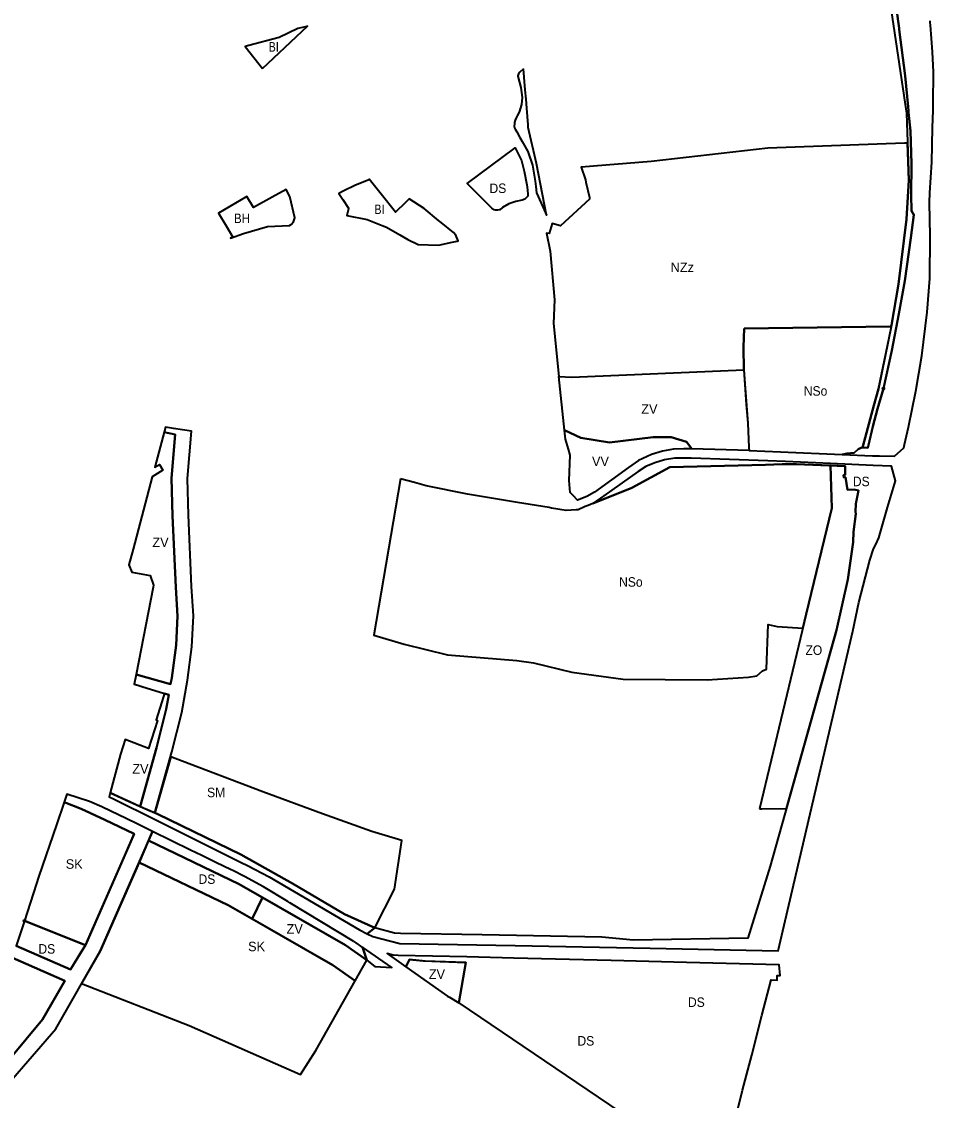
# Model space of a CAD drawing. Extents: x -650276 to -642489, y -1074311 to -1066658.
# Drawn here: x -646121 to -644970, y -1071573 to -1070212 of the extents above; entities that cross this region are included whole.
import ezdxf

# ---------------------------------------------------------------- set-up
doc = ezdxf.new("R2010")
doc.units = 0
doc.header["$LTSCALE"] = 4.8
doc.header["$PDMODE"] = 32
doc.header["$PDSIZE"] = 2.4
for name, color, linetype, lineweight in [('1', 7, 'Continuous', 35), ('11', 7, 'Continuous', 35), ('15', 7, 'Continuous', 35), ('18', 7, 'Continuous', 35), ('2', 7, 'Continuous', 35), ('20', 7, 'Continuous', 35), ('24', 7, 'Continuous', 35), ('40', 7, 'Continuous', 35), ('42', 7, 'Continuous', 35), ('45', 7, 'Continuous', 35), ('46', 7, 'Continuous', 35), ('56', 7, 'Continuous', 35)]:
    doc.layers.add(name, color=color, linetype=linetype, lineweight=lineweight)
doc.layers.add('62', color=7, linetype='Continuous')
doc.layers.add('63', color=7, linetype='Continuous')

msp = doc.modelspace()

# ---------------------------------------------------------------- linework, layer by layer
at = {"layer": '1'}
msp.add_lwpolyline([(-645862.66, -1070469.5), (-645853.98, -1070483.81), (-645856.87, -1070485.24), (-645840.59, -1070479), (-645810.44, -1070470.17), (-645782.57, -1070469.22), (-645780.38, -1070467.64), (-645777.8, -1070464.4), (-645776.04, -1070459.38), (-645782.13, -1070432.59), (-645786.9, -1070423.81), (-645804.58, -1070433.53), (-645828.24, -1070446.54), (-645836.32, -1070432.55), (-645872.35, -1070453.55)], close=True, dxfattribs=at)
at = {"layer": '11'}
msp.add_lwpolyline([(-646066.165, -1071422.155), (-646153.5, -1071383.85), (-646208.577, -1071360.044), (-646241.68, -1071416.887), (-646258.487, -1071439.265), (-646275.615, -1071460.886), (-646289.976, -1071477.514), (-646330.914, -1071521.11), (-646324, -1071535), (-646217.978, -1071613.552), (-646211.407, -1071606.247), (-646156.471, -1071545.166), (-646094.063, -1071471.007)], close=True, dxfattribs=at)
at = {"layer": '15'}
for points in [[(-645065.235, -1070011.695), (-645056.555, -1070026.163), (-645050.293, -1070047.035), (-645043.92, -1070076.344), (-645034.122, -1070126.616), (-645004.791, -1070324.889), (-645004.523, -1070326.697)], [(-645033.53, -1070674.55), (-645022.64, -1070626.93), (-645014.07, -1070580.72), (-645006.44, -1070538.78), (-644998.92, -1070484.58), (-644995.14, -1070455.72), (-644998.17, -1070450.59), (-644998.25, -1070430.5), (-644997.87, -1070391.16), (-644999.47, -1070349.63), (-645001.64, -1070326.4), (-645001.81, -1070324.58), (-645002.308, -1070319.268), (-645005.98, -1070280.14), (-645013.51, -1070222.04), (-645013.77, -1070220.04), (-645016.92, -1070196.32)], [(-645487.361, -1070271.37), (-645491.94, -1070275.85), (-645491.94, -1070275.85), (-645493.8, -1070277.67), (-645494.57, -1070280.34), (-645494.12, -1070282.52), (-645490.79, -1070294.93), (-645489.31, -1070307.77), (-645490.03, -1070316.27), (-645493.05, -1070326.11), (-645495.44, -1070330.67), (-645496.12, -1070332.34), (-645497.83, -1070336.16), (-645498.75, -1070338.98), (-645499.01, -1070340.96), (-645499.09, -1070343.91), (-645498.74, -1070345.87), (-645498, -1070347.74), (-645496.02, -1070351.15), (-645491.97, -1070358.14), (-645488.99, -1070362.96)], [(-645487.361, -1070271.37), (-645491.94, -1070275.85), (-645491.94, -1070275.85), (-645493.8, -1070277.67), (-645494.57, -1070280.34), (-645494.12, -1070282.52), (-645490.79, -1070294.93), (-645489.31, -1070307.77), (-645490.03, -1070316.27), (-645493.05, -1070326.11), (-645495.44, -1070330.67), (-645496.12, -1070332.34), (-645497.83, -1070336.16), (-645498.75, -1070338.98), (-645499.01, -1070340.96), (-645499.09, -1070343.91), (-645498.74, -1070345.87), (-645498, -1070347.74), (-645496.02, -1070351.15), (-645491.97, -1070358.14)], [(-645458.32, -1070455.91), (-645471, -1070391), (-645481.67, -1070345.39), (-645481.65, -1070342.07), (-645483.34, -1070321.17), (-645484.27, -1070309.7), (-645485.21, -1070298.03), (-645487.361, -1070271.37)], [(-645483.34, -1070321.17), (-645484.27, -1070309.7), (-645485.21, -1070298.03), (-645487.361, -1070271.37)], [(-645482.16, -1070375.96), (-645476.12, -1070393.13), (-645472.61, -1070413.13), (-645471.87, -1070419.96), (-645470.99, -1070428.07), (-645461.32, -1070449.31), (-645458.32, -1070455.91), (-645471, -1070391), (-645481.67, -1070345.39), (-645481.65, -1070342.07), (-645483.34, -1070321.17)], [(-645004.523, -1070326.697), (-645004.434, -1070327.302), (-645001.312, -1070412.099), (-645004.327, -1070461.264), (-645014.277, -1070543.11), (-645023.048, -1070595.033), (-645039.574, -1070675.065)], [(-645491.97, -1070358.14), (-645488.99, -1070362.96), (-645482.16, -1070375.96)], [(-645488.99, -1070362.96), (-645482.16, -1070375.96), (-645476.12, -1070393.13), (-645472.61, -1070413.13), (-645471.87, -1070419.96), (-645470.99, -1070428.07), (-645461.32, -1070449.31), (-645458.32, -1070455.91)], [(-645039.574, -1070675.065), (-645045.493, -1070696.321), (-645059.308, -1070747.712), (-645059.403, -1070749.195), (-645053.21, -1070749.75), (-645052.4, -1070746.427), (-645046.63, -1070722.77), (-645041, -1070700.44), (-645033.53, -1070674.55)], [(-646197.398, -1071620.579), (-646077.593, -1071482.499), (-646021.674, -1071384.575), (-645964.396, -1071254.314), (-645955.342, -1071233.725), (-645973.324, -1071224.925), (-645989.7, -1071216.91), (-645997.62, -1071213.03), (-646019.41, -1071202.36), (-646035.06, -1071195.87), (-646063.59, -1071186.33), (-646067.097, -1071196.699), (-646045.462, -1071204.917), (-646015.387, -1071218.854), (-645978.403, -1071236.481), (-646040.084, -1071376.813), (-646058.719, -1071407.796), (-646127.301, -1071378.036)], [(-645701.44, -1071372.25), (-645782.32, -1071323.5), (-645784.92, -1071321.93), (-645815.65, -1071303.41), (-645839.37, -1071290.6), (-645854.1, -1071282.93), (-645856.26, -1071281.91), (-645875.48, -1071272.81), (-645893.41, -1071264.04), (-645907.62, -1071257.08), (-645955.342, -1071233.725), (-645960.34, -1071245.09), (-645846, -1071300), (-645712, -1071377), (-645712, -1071377)], [(-645712, -1071377), (-645685.098, -1071395.824), (-645690.677, -1071379.721)], [(-646132.229, -1071393.179), (-646066.165, -1071422.155), (-646094.063, -1071471.007), (-646156.471, -1071545.166)]]:
    msp.add_lwpolyline(points, dxfattribs=at)
for points in [[(-645911.345, -1070788.463), (-645906.373, -1070728.716), (-645929.077, -1070725.068), (-645939.27, -1070723.43), (-645940.955, -1070729.799), (-645926.784, -1070732.812), (-645931.369, -1070787.913), (-645930.036, -1070835.367), (-645926.084, -1070925.481), (-645923.919, -1070961.855), (-645925.626, -1070998.754), (-645931.24, -1071039.686), (-645932.635, -1071047.688), (-645976.17, -1071035.39), (-645978.58, -1071047.68), (-645973.77, -1071049.17), (-645968.97, -1071050.66), (-645940.25, -1071059.59), (-645934.978, -1071061.119), (-645938.15, -1071079.311), (-645950.283, -1071128.057), (-645970.966, -1071202.169), (-645952.419, -1071210.117), (-645930.943, -1071133.161), (-645918.57, -1071083.449), (-645911.474, -1071042.764), (-645905.69, -1071000.578), (-645903.891, -1070961.723), (-645906.11, -1070924.449), (-645910.048, -1070834.649)], [(-645694.15, -1071357.83), (-645684.785, -1071362.539), (-645674.947, -1071355.071), (-645713.428, -1071337.765), (-645778.69, -1071299.362), (-645844.079, -1071262.487), (-645948.761, -1071211.885), (-645967, -1071204), (-646008.714, -1071184.746), (-646010.14, -1071190.08), (-646004.65, -1071192.55), (-645951.118, -1071219.11), (-645843.45, -1071272.53), (-645835.76, -1071276.35), (-645808.13, -1071290.78), (-645795.97, -1071297.93), (-645694.15, -1071357.83)]]:
    msp.add_lwpolyline(points, close=True, dxfattribs=at)
msp.add_arc((-645538.107, -1071148.434), 277.076, 233.87926, 236.5888, dxfattribs=at)
msp.add_point((-645033.53, -1070674.55), dxfattribs=at)
at = {"layer": '18'}
for points in [[(-645926.81, -1071141.595), (-645932.502, -1071139.426), (-645952.419, -1071210.117), (-645948.761, -1071211.885)], [(-645678.86, -1071233.58), (-645741.09, -1071211.36), (-645816.47, -1071183.63), (-645926.81, -1071141.595)], [(-645948.761, -1071211.885), (-645844.079, -1071262.487), (-645778.69, -1071299.362), (-645713.428, -1071337.765), (-645674.947, -1071355.071)], [(-645674.947, -1071355.071), (-645650.09, -1071306.433), (-645640.737, -1071244.963), (-645678.86, -1071233.58)]]:
    msp.add_lwpolyline(points, dxfattribs=at)
at = {"layer": '2'}
for points in [[(-645816.9, -1070270.96), (-645760.05, -1070217.79), (-645760.91, -1070217.98), (-645772.08, -1070220.39), (-645795.85, -1070231.81), (-645833.92, -1070241.96), (-645838.53, -1070243.19)], [(-645594.769, -1070494.065), (-645577.47, -1070490.3), (-645571.13, -1070488.89), (-645569.97, -1070488.3), (-645572.86, -1070481.41), (-645575.7, -1070477.77), (-645591.49, -1070465.19), (-645594.62, -1070462.7), (-645612.77, -1070447.82), (-645631.63, -1070435.3), (-645636.42, -1070439.93), (-645648.9, -1070452.38), (-645666.99, -1070429.58), (-645682.02, -1070410.65), (-645683.52, -1070411.71), (-645699.33, -1070418.25), (-645714.74, -1070425.84), (-645720.48, -1070428.75), (-645715.56, -1070436.27), (-645708.28, -1070447.28), (-645708.42, -1070447.94), (-645710.14, -1070456.31), (-645684.78, -1070461.52), (-645665.6, -1070469.04), (-645660.29, -1070471.12), (-645643.4, -1070481.02), (-645633.35, -1070486.91), (-645620.22, -1070493)]]:
    msp.add_lwpolyline(points, close=True, dxfattribs=at)
at = {"layer": '20'}
for points in [[(-645990.48, -1071263.958), (-645978.403, -1071236.481), (-646015.387, -1071218.854), (-646045.462, -1071204.917), (-646067.097, -1071196.699), (-646076.713, -1071225.138)], [(-646076.713, -1071225.138), (-646098.66, -1071290.03), (-646102.011, -1071300.326), (-646117.031, -1071346.48)], [(-646117.031, -1071346.48), (-646040.084, -1071376.813), (-645990.48, -1071263.958)]]:
    msp.add_lwpolyline(points, dxfattribs=at)
msp.add_lwpolyline([(-645699.825, -1071422.134), (-645728.105, -1071402.346), (-645859.986, -1071326.563), (-645972.422, -1071272.568), (-646021.674, -1071384.575), (-646044.948, -1071425.333), (-645909.13, -1071478.56), (-645768.62, -1071540.17), (-645749.631, -1071509.908)], close=True, dxfattribs=at)
msp.add_point((-646117.031, -1071346.48), dxfattribs=at)
at = {"layer": '24'}
for points in [[(-645016.92, -1070196.32), (-645013.77, -1070220.04), (-645013.51, -1070222.04), (-645005.98, -1070280.14), (-645002.308, -1070319.268), (-645001.81, -1070324.58), (-645001.64, -1070326.4), (-644999.47, -1070349.63), (-644997.87, -1070391.16), (-644998.25, -1070430.5), (-644998.17, -1070450.59), (-644995.14, -1070455.72), (-644998.92, -1070484.58), (-645006.44, -1070538.78), (-645014.07, -1070580.72), (-645022.64, -1070626.93), (-645033.53, -1070674.55)], [(-645033.53, -1070674.55), (-645041, -1070700.44), (-645046.63, -1070722.77), (-645052.4, -1070746.427), (-645053.21, -1070749.75), (-645060.46, -1070749.1), (-645065.17, -1070751.39), (-645070.3, -1070755.92), (-645079.38, -1070756.91), (-645085.58, -1070758.04), (-645047.39, -1070759.71), (-645038.44, -1070759.83), (-645019.57, -1070760.07), (-645007.68, -1070749.5), (-645006.739, -1070745.384), (-645001.71, -1070723.39), (-644997.14, -1070700.88), (-644992.6, -1070677.92), (-644985.04, -1070633.43), (-644978.44, -1070578.56), (-644975.05, -1070536.16), (-644974.44, -1070482.48), (-644975.29, -1070440.14), (-644974.69, -1070427.86), (-644972.48, -1070389.15), (-644971.37, -1070345.98), (-644970.61, -1070323.44), (-644970.55, -1070321.56), (-644970.524, -1070315.358), (-644970.36, -1070275.49), (-644971.47, -1070250.14), (-644974, -1070216.2), (-644974.29, -1070213.17), (-644974.49, -1070210.98)], [(-645222.48, -1071606.08), (-645211.27, -1071560.01), (-645199.61, -1071515.68), (-645186.67, -1071465.55), (-645175.06, -1071420.93), (-645167.58, -1071421.19), (-645167.37, -1071415.2), (-645163.56, -1071415.3), (-645164.76, -1071401.79), (-645281.92, -1071398.82), (-645376.87, -1071396.41), (-645499.65, -1071393.3), (-645558.9, -1071391.8), (-645645.368, -1071389.96), (-645651.93, -1071389.82), (-645659.6, -1071387.71), (-645647.727, -1071396.036), (-645635.795, -1071404.403), (-645631.44, -1071394.9), (-645614.201, -1071396.844), (-645560.11, -1071398.7), (-645569.07, -1071449.88), (-645501.37, -1071495.68), (-645393.34, -1071568.75), (-645324.17, -1071615.53)]]:
    msp.add_lwpolyline(points, dxfattribs=at)
for points in [[(-645497.81, -1070370.93), (-645497.81, -1070370.93), (-645490.19, -1070386.97), (-645486.54, -1070400.38), (-645483.29, -1070417.99), (-645482.62, -1070423.93), (-645481.93, -1070430.04), (-645482.18, -1070432.13), (-645485.67, -1070435.7), (-645489.34, -1070437.05), (-645497.33, -1070438.82), (-645505.88, -1070441.74), (-645513.81, -1070446.24), (-645517.44, -1070449.23), (-645517.95, -1070449.45), (-645520.4, -1070449.87), (-645521.41, -1070449.84), (-645522.95, -1070449.61), (-645524.42, -1070449.16), (-645525.75, -1070448.41), (-645527.34, -1070447.1), (-645558.36, -1070416.1)], [(-645081.85, -1070781.59), (-645081.57, -1070783.53), (-645083.95, -1070783.89), (-645083.49, -1070786.92), (-645081.13, -1070786.56), (-645081.13, -1070786.56), (-645078.85, -1070802.46), (-645070.2, -1070802.33), (-645065.01, -1070803.22), (-645068.07, -1070820.37), (-645068.52, -1070830.52), (-645068.07, -1070832.72), (-645071.18, -1070855.63), (-645071.77, -1070868.73), (-645078.23, -1070915.65), (-645092.67, -1070979.52), (-645176.14, -1071277.26), (-645204.341, -1071368.19), (-645348.55, -1071370.559), (-645388.619, -1071366.991), (-645539.738, -1071364.092), (-645642.431, -1071362.259), (-645650.28, -1071362.07), (-645674.947, -1071355.071), (-645684.785, -1071362.539), (-645677.58, -1071366.16), (-645643.56, -1071374.75), (-645497.84, -1071377.53), (-645327.76, -1071380.76), (-645166.34, -1071384.07), (-645071.99, -1070980.72), (-645064.39, -1070944.7), (-645050.47, -1070891.48), (-645045.74, -1070877.19), (-645043, -1070871.35), (-645039.25, -1070863.33), (-645028.25, -1070824.83), (-645018.18, -1070791.34), (-645023.25, -1070772.62), (-645046.46, -1070771.98), (-645100.32, -1070769.5), (-645156.988, -1070766.884), (-645179.18, -1070765.86), (-645275.8, -1070762.66), (-645296.51, -1070762.52), (-645309.78, -1070764.88), (-645321.9, -1070768.47), (-645333.12, -1070773.33), (-645342.94, -1070779.31), (-645385.99, -1070810.35), (-645400.05, -1070819.84), (-645351, -1070800), (-645303, -1070774), (-645182, -1070771), (-645161, -1070770), (-645143, -1070770), (-645081.75, -1070772.79)], [(-645829.706, -1071343.963), (-645816.714, -1071316.828), (-645846, -1071300), (-645960.34, -1071245.09), (-645972.422, -1071272.568), (-645859.986, -1071326.563)], [(-646045.393, -1071385.64), (-646040.084, -1071376.813), (-646117.031, -1071346.48), (-646127.301, -1071378.036), (-646058.719, -1071407.796)], [(-645675.177, -1071403.922), (-645675.177, -1071403.922), (-645653.742, -1071405.36), (-645690.677, -1071379.721), (-645685.098, -1071395.824)]]:
    msp.add_lwpolyline(points, close=True, dxfattribs=at)
msp.add_point((-645033.53, -1070674.55), dxfattribs=at)
at = {"layer": '40'}
for points in [[(-645442.836, -1070659.455), (-645426.34, -1070660.33), (-645209.41, -1070651.2), (-645206.7, -1070694.76), (-645204.66, -1070718.51), (-645203.13, -1070749.36), (-645202.96, -1070752.89), (-645275.236, -1070750.954), (-645282, -1070742), (-645301, -1070736), (-645324, -1070736), (-645379, -1070743), (-645415, -1070737), (-645435.711, -1070727.497)], [(-645932.635, -1071047.688), (-645931.24, -1071039.686), (-645925.626, -1070998.754), (-645923.919, -1070961.855), (-645926.084, -1070925.481), (-645930.036, -1070835.367), (-645931.369, -1070787.913), (-645926.784, -1070732.812), (-645940.955, -1070729.799), (-645952.65, -1070773.98), (-645946.81, -1070770.47), (-645942.3, -1070777.96), (-645955.86, -1070786.21), (-645980.01, -1070877.28), (-645985.28, -1070897.13), (-645981.48, -1070906.35), (-645958.21, -1070910.84), (-645954.01, -1070922.8), (-645954.492, -1070925.251), (-645976.17, -1071035.39)], [(-645970.966, -1071202.169), (-645950.283, -1071128.057), (-645938.15, -1071079.311), (-645934.978, -1071061.119), (-645940.25, -1071059.59), (-645941.45, -1071063.3), (-645950.96, -1071092.8), (-645949.21, -1071093.62), (-645960.66, -1071128.71), (-645990.14, -1071117.76), (-645995.74, -1071136.22), (-646008.714, -1071184.746)], [(-645712, -1071377), (-645816.714, -1071316.828), (-645829.706, -1071343.963), (-645728.105, -1071402.346), (-645699.825, -1071422.134), (-645685.098, -1071395.824)], [(-645583.18, -1071441.3), (-645580.947, -1071442.658), (-645569.07, -1071449.88), (-645560.11, -1071398.7), (-645611.58, -1071397.14), (-645631.44, -1071394.9), (-645635.795, -1071404.403)]]:
    msp.add_lwpolyline(points, close=True, dxfattribs=at)
at = {"layer": '42'}
for points in [[(-645155.777, -1071204.626), (-645092.67, -1070979.52), (-645078.23, -1070915.65), (-645071.77, -1070868.73), (-645071.18, -1070855.63), (-645068.07, -1070832.72), (-645068.52, -1070830.52), (-645068.07, -1070820.37), (-645065.01, -1070803.22), (-645070.2, -1070802.33), (-645078.85, -1070802.46), (-645081.13, -1070786.56), (-645081.13, -1070786.56), (-645083.49, -1070786.92), (-645083.95, -1070783.89), (-645081.57, -1070783.53), (-645081.85, -1070781.59), (-645081.75, -1070772.79), (-645100.268, -1070771.946)], [(-645100.268, -1070771.946), (-645098.438, -1070825.558), (-645130.749, -1070959.561)], [(-645130.749, -1070959.561), (-645130.749, -1070959.561), (-645189.902, -1071204.885)], [(-645189.902, -1071204.885), (-645186.64, -1071204.86), (-645155.777, -1071204.626)]]:
    msp.add_lwpolyline(points, dxfattribs=at)
at = {"layer": '45'}
msp.add_lwpolyline([(-645275.236, -1070750.954), (-645285.11, -1070750.69), (-645298.41, -1070751.48), (-645312.2, -1070753.77), (-645325.82, -1070757.94), (-645342.41, -1070765.76), (-645354.98, -1070774.28), (-645398.04, -1070805.44), (-645407.37, -1070810.95), (-645419.18, -1070815.44), (-645424.969, -1070809.563), (-645428.39, -1070806.09), (-645430, -1070790.68), (-645428.73, -1070758.67), (-645430.84, -1070751.43), (-645434.53, -1070738.77), (-645435.711, -1070727.497), (-645415, -1070737), (-645379, -1070743), (-645324, -1070736), (-645301, -1070736), (-645282, -1070742)], close=True, dxfattribs=at)
at = {"layer": '46'}
for points in [[(-645023.048, -1070595.033), (-645014.277, -1070543.11), (-645004.327, -1070461.264), (-645001.312, -1070412.099), (-645003.03, -1070365.427), (-645003.102, -1070365.432), (-645006.86, -1070365.38), (-645179.26, -1070371.74), (-645326.62, -1070388.32), (-645414.65, -1070395.37), (-645409.38, -1070411.41), (-645408.66, -1070414.62), (-645404.34, -1070433.93), (-645404.4, -1070435.88), (-645440.61, -1070469.53), (-645451.226, -1070466.394), (-645455.09, -1070479.21), (-645458.46, -1070478.86), (-645454.02, -1070501.52), (-645448.36, -1070563), (-645449.82, -1070592.72), (-645442.834, -1070659.455)], [(-645208.96, -1070599.22), (-645025.12, -1070596.42), (-645023.346, -1070596.478), (-645023.048, -1070595.033)], [(-645209.41, -1070651.2), (-645209.79, -1070622.69), (-645208.96, -1070599.22)], [(-645442.834, -1070659.455), (-645426.34, -1070660.33), (-645209.41, -1070651.2)]]:
    msp.add_lwpolyline(points, dxfattribs=at)
at = {"layer": '56'}
msp.add_line((-645207.88, -1070674.2), (-645204.66, -1070718.51), dxfattribs=at)
msp.add_lwpolyline([(-645208.96, -1070599.22), (-645209.79, -1070622.69), (-645209.41, -1070651.2), (-645207.88, -1070674.2), (-645204.66, -1070718.51), (-645203.13, -1070749.36), (-645202.96, -1070752.89), (-645163.06, -1070754.64), (-645085.58, -1070758.04), (-645079.38, -1070756.91), (-645070.3, -1070755.92), (-645065.17, -1070751.39), (-645060.46, -1070749.1), (-645059.421, -1070749.039), (-645059.308, -1070747.712), (-645045.493, -1070696.321), (-645039.574, -1070675.065), (-645028.384, -1070620.876), (-645023.346, -1070596.478), (-645025.12, -1070596.42)], close=True, dxfattribs=at)
for points in [[(-645023.346, -1070596.478), (-645025.12, -1070596.42), (-645208.96, -1070599.22)], [(-645208.96, -1070599.22), (-645209.79, -1070622.69), (-645209.41, -1070651.2), (-645207.88, -1070674.2)], [(-645060.46, -1070749.1), (-645059.421, -1070749.039), (-645059.308, -1070747.712), (-645045.493, -1070696.321), (-645039.574, -1070675.065), (-645039.338, -1070673.923), (-645023.346, -1070596.478)], [(-645204.66, -1070718.51), (-645203.13, -1070749.36), (-645202.96, -1070752.89)], [(-645202.96, -1070752.89), (-645163.06, -1070754.64), (-645085.58, -1070758.04), (-645079.38, -1070756.91), (-645070.3, -1070755.92), (-645065.17, -1070751.39), (-645060.46, -1070749.1)], [(-645100.268, -1070771.946), (-645143, -1070770), (-645161, -1070770), (-645182, -1070771), (-645303, -1070774), (-645351, -1070800), (-645400.05, -1070819.84), (-645406.09, -1070822.34), (-645409.52, -1070823.76), (-645418.67, -1070827.72), (-645421.09, -1070827.89), (-645433.49, -1070828.76), (-645452.31, -1070825.52), (-645455.184, -1070825.042)], [(-645130.749, -1070959.561), (-645098.438, -1070825.558), (-645100.268, -1070771.946)], [(-645642.52, -1070788.7), (-645676.292, -1070985.89), (-645637.94, -1070997.4), (-645583.18, -1071010.7), (-645495.87, -1071017.81)], [(-645455.184, -1070825.042), (-645494.82, -1070818.45), (-645558.3, -1070808), (-645610.25, -1070797.55), (-645625, -1070793.5), (-645642.52, -1070788.7)], [(-645495.87, -1071017.81), (-645475.01, -1071020.72), (-645426.38, -1071032.8), (-645361.54, -1071041.54), (-645255.93, -1071042.36), (-645203.66, -1071038.81), (-645193.24, -1071037.31), (-645186.18, -1071030.83), (-645180.72, -1071028.86), (-645178.73, -1070972.35), (-645167.47, -1070975.2), (-645134.973, -1070977.077), (-645134.973, -1070977.077), (-645130.749, -1070959.561)]]:
    msp.add_lwpolyline(points, dxfattribs=at)

# ---------------------------------------------------------------- texts
at = {"layer": '62'}
for s, width, p in [('BI', 0.85, (-645808.987, -1070249.726)), ('DS', 0.95, (-645530.386, -1070428.148)), ('BH', 0.9, (-645852.646, -1070466.101)), ('DS', 0.95, (-645072.003, -1070798.001)), ('ZO', 0.95, (-645131.758, -1071010.853)), ('SM', 0.95, (-645886.606, -1071190.345)), ('DS', 0.95, (-645897.407, -1071299.717)), ('DS', 0.95, (-646099.407, -1071387.717)), ('DS', 0.95, (-645279.957, -1071454.984)), ('DS', 0.95, (-645419.407, -1071503.717))]:
    msp.add_text(s, height=12, dxfattribs=dict(at, width=width)).set_placement(p)
for s, p in [('ZV', (-645955.588, -1070874.768)), ('ZV', (-645980.931, -1071160.591)), ('SK', (-646064.883, -1071280.659)), ('ZV', (-645786.398, -1071362.507)), ('SK', (-645834.883, -1071384.659)), ('ZV', (-645606.931, -1071419.591))]:
    msp.add_text(s, height=12, dxfattribs=at).set_placement(p)
at = {"layer": '63'}
for s, width, p in [('BI', 0.85, (-645675.657, -1070454.713)), ('NSo', 0.95, (-645133.866, -1070683.823)), ('NSo', 0.95, (-645366.866, -1070924.823))]:
    msp.add_text(s, height=12, dxfattribs=dict(at, width=width)).set_placement(p)
for s, p in [('NZz', (-645301.866, -1070527.823)), ('ZV', (-645338.931, -1070706.591)), ('VV', (-645401.075, -1070772.614))]:
    msp.add_text(s, height=12, dxfattribs=at).set_placement(p)

doc.saveas('drawing.dxf')
